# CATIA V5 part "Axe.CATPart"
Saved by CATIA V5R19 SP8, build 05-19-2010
Part number: Axe
Publications: "Rayon_axe", "Demilongue_entre_circlips"
Bounding box of the stored display mesh (mm): x -23 to 23, y -12.358 to 12.358, z -12.5 to 12.5
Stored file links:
  F:\! CONCEPTION\PROJET\Mécanisme 590\CAO\Axe.CATPart
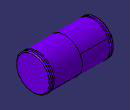
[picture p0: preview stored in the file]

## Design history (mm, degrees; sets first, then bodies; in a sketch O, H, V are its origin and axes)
Parameters
  Rayon_axe = 12.5 mm
  Demilongue_entre_circlips = 20 mm
Body1 (main body)
  Sketch1 on xy-plane, origin (0, 0, 0), H (1, 0, 0), V (0, 1, 0)
    point P1 (-23, 0)
    line L1 (-23, 0) -> (-23, 11.7929)
    line L2 (-23, 11.7929) -> (-22.2929, 12.5)
    line L3 (-22.2929, 12.5) -> (-21, 12.5)
    line L4 (-21, 12.5) -> (-21, 10.5)
    line L5 (-21, 10.5) -> (-20, 10.5)
    line L6 (-20, 10.5) -> (-20, 12.5)
    point P7 (-20, 12.5)
    line L7 (-20, 12.5) -> (0, 12.5)
    point P8 (0, 12.5)
    line L8 (0, 12.5) -> (0, 0)
    line L9 (0, 0) -> (-23, 0)
    distance L7 L9 = 12.5 {= Rayon_axe}
    distance L4 L6 = 1
    distance L5 L7 = 2
    angle L2 L1 = 45
    length L2 = 1
    distance L4 L1 = 2
    distance L6 V = 20 {= Demilongue_entre_circlips}
    coincidence: P1 H, P7 L3, P8 V
    vertical: L1 V, L4 V, L6 V, L8 V
    horizontal: L3 H, L5 H, L7 H, L9 H
  Shaft1: profile Sketch1, axis Sketch1.H, angle 360
  Mirror1: of Shaft1, about yz-plane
